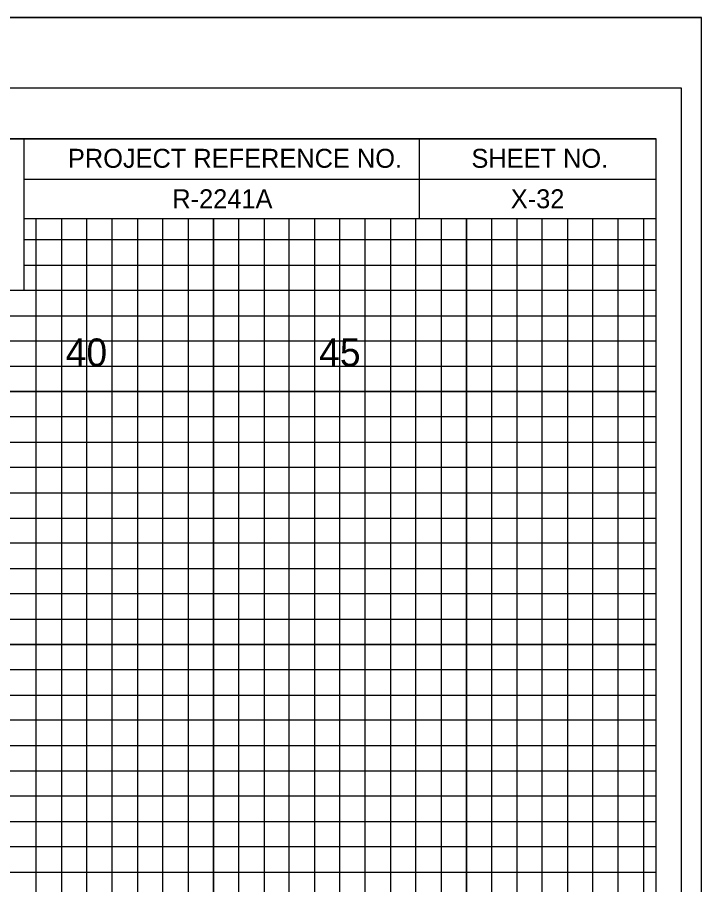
# Model space of a CAD drawing. Extents: x -4 to 103, y -2 to 6583.
# Drawn here: x 89.88 to 103.4, y 2245.83 to 2262.97 of the extents above; entities that cross this region are included whole.
import ezdxf

# ---------------------------------------------------------------- set-up
doc = ezdxf.new("R2010")
doc.units = 0
for name, color, linetype in [('Prop XS Offset Labels', 7, 'Continuous'), ('Prop XS Project Number', 7, 'Continuous'), ('Prop XS Sheet Number', 7, 'Continuous'), ('Sheet Cross Section CELL', 7, 'Continuous'), ('Sheet Cross Section Grid Major CELL', 7, 'Continuous'), ('Sheet Cross Section Grid Middle CELL', 7, 'Continuous'), ('Sheet Cutting Line CELL', 7, 'Continuous'), ('Sheet DOT Grid CELL', 7, 'Continuous'), ('Sheet Plot Border Inside CELL', 7, 'Continuous'), ('Sheet Plot Border Outside CELL', 7, 'Continuous')]:
    doc.layers.add(name, color=color, linetype=linetype)

msp = doc.modelspace()

# ---------------------------------------------------------------- linework, layer by layer
at = {"layer": 'Sheet Cross Section CELL'}
for p, q in [((90, 2260.575), (102.5, 2260.575)), ((90, 2260.575), (102.5, 2260.575)), ((97.825, 2259), (97.825, 2260.575)), ((101.875, 2260.575), (101.875, 2260.575)), ((102.5, 2260.575), (102.5, 2260.575)), ((102.5, 2259), (102.5, 2260.575)), ((102.5, 2260.575), (102.5, 2260.575)), ((102.5, 2260.575), (102.5, 2260.575)), ((102.5, 2259), (102.5, 2260.575)), ((90, 2259.775), (102.5, 2259.775)), ((90, 2259), (102.5, 2259)), ((99.4, 2259), (99.4, 2259)), ((99.4, 2259), (99.4, 2259))]:
    msp.add_line(p, q, dxfattribs=at)
for points in [[(102.5, 2260.575), (0, 2260.575), (0, 2195.575), (102.5, 2195.575)], [(83.75, 2260.575), (90, 2260.575), (90, 2257.575), (83.75, 2257.575)]]:
    msp.add_lwpolyline(points, close=True, dxfattribs=at)
at = {"layer": 'Sheet Cross Section Grid Major CELL'}
for points in [[(91.25, 2195.575), (91.25, 2259), (93.75, 2259), (93.75, 2195.575)], [(96.25, 2195.575), (96.25, 2259), (98.75, 2259), (98.75, 2195.575)], [(101.25, 2195.575), (101.25, 2259)], [(90, 2258.075), (102.5, 2258.075)], [(0, 2253.075), (102.5, 2253.075), (102.5, 2255.575), (0, 2255.575)], [(0, 2248.075), (102.5, 2248.075), (102.5, 2250.575), (0, 2250.575)]]:
    msp.add_lwpolyline(points, dxfattribs=at)
at = {"layer": 'Sheet Cross Section Grid Middle CELL'}
for points in [[(90.25, 2195.575), (90.25, 2259), (90.75, 2259), (90.75, 2195.575)], [(91.75, 2195.575), (91.75, 2259), (92.25, 2259), (92.25, 2195.575)], [(92.75, 2195.575), (92.75, 2259), (93.25, 2259), (93.25, 2195.575)], [(94.25, 2195.575), (94.25, 2259), (94.75, 2259), (94.75, 2195.575)], [(95.25, 2195.575), (95.25, 2259), (95.75, 2259), (95.75, 2195.575)], [(96.75, 2195.575), (96.75, 2259), (97.25, 2259), (97.25, 2195.575)], [(97.75, 2195.575), (97.75, 2259), (98.25, 2259), (98.25, 2195.575)], [(99.25, 2195.575), (99.25, 2259), (99.75, 2259), (99.75, 2195.575)], [(100.25, 2195.575), (100.25, 2259)], [(100.25, 2259), (100.75, 2259), (100.75, 2195.575), (101.75, 2195.575), (101.75, 2259), (102.25, 2259), (102.25, 2195.575)], [(102.5, 2257.575), (102.5, 2258.575), (90, 2258.575)], [(0, 2257.075), (102.5, 2257.075), (102.5, 2257.575), (0, 2257.575)], [(0, 2256.075), (102.5, 2256.075), (102.5, 2256.575), (0, 2256.575)], [(0, 2254.575), (102.5, 2254.575), (102.5, 2255.075), (0, 2255.075)], [(0, 2253.575), (102.5, 2253.575), (102.5, 2254.075), (0, 2254.075)], [(0, 2252.075), (102.5, 2252.075), (102.5, 2252.575), (0, 2252.575)], [(0, 2251.075), (102.5, 2251.075), (102.5, 2251.575), (0, 2251.575)], [(0, 2249.575), (102.5, 2249.575), (102.5, 2250.075), (0, 2250.075)], [(0, 2248.575), (102.5, 2248.575), (102.5, 2249.075), (0, 2249.075)], [(0, 2247.075), (102.5, 2247.075), (102.5, 2247.575), (0, 2247.575)], [(0, 2246.075), (102.5, 2246.075), (102.5, 2246.575), (0, 2246.575)]]:
    msp.add_lwpolyline(points, dxfattribs=at)
at = {"layer": 'Sheet Cutting Line CELL'}
msp.add_line((-3.5, 2262.975), (103.4, 2262.975), dxfattribs=at)
at = {"layer": 'Sheet DOT Grid CELL'}
for p, q in [((91.25, 2195.575), (91.25, 2259)), ((93.75, 2195.575), (93.75, 2259)), ((96.25, 2195.575), (96.25, 2259)), ((98.75, 2195.575), (98.75, 2259)), ((101.25, 2195.575), (101.25, 2259)), ((90, 2258.075), (102.5, 2258.075)), ((0, 2255.575), (102.5, 2255.575)), ((0, 2253.075), (102.5, 2253.075)), ((0, 2250.575), (102.5, 2250.575)), ((0, 2248.075), (102.5, 2248.075))]:
    msp.add_line(p, q, dxfattribs=at)
at = {"layer": 'Sheet Plot Border Inside CELL'}
msp.add_lwpolyline([(103, 2261.575), (-2.8, 2261.575), (-2.8, 2194.575), (103, 2194.575)], close=True, dxfattribs=at)
at = {"layer": 'Sheet Plot Border Outside CELL'}
msp.add_lwpolyline([(103.4, 2262.975), (-3.5, 2262.975), (-3.5, 2193.15), (103.4, 2193.15)], close=True, dxfattribs=at)

# ---------------------------------------------------------------- texts
at = {"layer": 'Prop XS Offset Labels'}
for s, p in [('40', (90.831, 2256.075)), ('45', (95.84, 2256.075))]:
    msp.add_text(s, height=0.55, dxfattribs=at).set_placement(p)
at = {"layer": 'Prop XS Project Number'}
msp.add_text('R-2241A', height=0.375, dxfattribs=at).set_placement((92.938, 2259.2))
at = {"layer": 'Prop XS Sheet Number'}
msp.add_text('X-32', height=0.375, dxfattribs=at).set_placement((99.628, 2259.2))
at = {"layer": 'Sheet Cross Section CELL'}
for s, p in [('PROJECT REFERENCE NO.', (90.875, 2260)), ('SHEET NO.', (98.85, 2260))]:
    msp.add_text(s, height=0.375, dxfattribs=at).set_placement(p)

doc.saveas('drawing.dxf')
